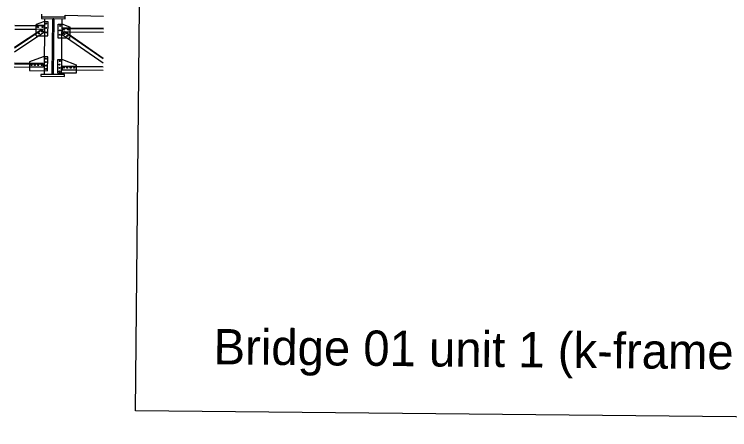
# Model space of a CAD drawing. Extents: x 632066 to 633140, y 373235 to 381884.
# Drawn here: x 632255.8 to 632316.5, y 378317.1 to 378352.4 of the extents above; entities that cross this region are included whole.
import ezdxf

# ---------------------------------------------------------------- set-up
doc = ezdxf.new("R2010")
doc.units = 0
for name, color, linetype in [('B_Boring', 7, 'Continuous'), ('B_Boring Annot', 7, 'Continuous'), ('R_Proposed Const Limits Cut', 7, 'Continuous'), ('R_Proposed Const Limits Fill', 7, 'Continuous'), ('USACE_Easement', 7, 'Continuous')]:
    doc.layers.add(name, color=color, linetype=linetype)

msp = doc.modelspace()

# ---------------------------------------------------------------- linework, layer by layer
at = {"layer": 'B_Boring'}
for p, q in [((632258.246, 378351.771), (632257.618, 378351.527)), ((632258.621, 378351.767), (632258.246, 378351.771)), ((632258.332, 378352.051), (632258.329, 378351.77)), ((632258.609, 378350.58), (632258.621, 378351.767)), ((632259.79, 378352.036), (632259.785, 378351.559)), ((632255.772, 378349.57), (632258.118, 378351.122)), ((632255.773, 378349.62), (632258.095, 378351.157)), ((632255.788, 378351.154), (632257.614, 378351.136)), ((632255.791, 378351.488), (632257.617, 378351.469)), ((632257.611, 378350.837), (632257.618, 378351.527)), ((632258.276, 378350.877), (632258.095, 378351.157)), ((632259.482, 378350.375), (632259.493, 378351.562)), ((632259.493, 378351.562), (632259.868, 378351.558)), ((632259.868, 378351.558), (632260.491, 378351.302)), ((632260.484, 378350.611), (632260.491, 378351.302)), ((632260.491, 378351.244), (632263.325, 378351.216)), ((632255.769, 378349.217), (632258.276, 378350.877)), ((632257.839, 378350.588), (632258.609, 378350.58)), ((632258.317, 378350.578), (632258.299, 378348.787)), ((632259.82, 378350.665), (632260.007, 378350.941)), ((632263.296, 378348.263), (632259.82, 378350.665)), ((632263.3, 378348.616), (632259.984, 378350.907)), ((632263.3, 378348.666), (632260.007, 378350.941)), ((632260.487, 378350.911), (632263.322, 378350.883)), ((632260.252, 378350.367), (632259.482, 378350.375)), ((632259.773, 378350.367), (632259.755, 378348.576)), ((632258.216, 378348.788), (632257.045, 378348.356)), ((632258.591, 378348.784), (632258.216, 378348.788)), ((632258.579, 378347.617), (632258.591, 378348.784)), ((632257.044, 378348.241), (632255.759, 378348.254)), ((632257.045, 378348.356), (632257.038, 378347.633)), ((632259.452, 378347.412), (632259.464, 378348.578)), ((632259.464, 378348.578), (632259.839, 378348.575)), ((632259.839, 378348.575), (632261.001, 378348.12)), ((632261.001, 378348.12), (632260.994, 378347.396)), ((632255.756, 378347.932), (632257.04, 378347.919)), ((632257.038, 378347.633), (632258.579, 378347.617)), ((632258.288, 378347.62), (632258.284, 378347.301)), ((632260.994, 378347.396), (632259.452, 378347.412)), ((632260.997, 378347.683), (632263.29, 378347.66)), ((632261, 378348.005), (632263.25, 378347.983)), ((632259.744, 378347.409), (632259.743, 378347.286))]:
    msp.add_line(p, q, dxfattribs=at)
for points in [[(632260.062, 378352.169), (632258.062, 378352.189), (632258.061, 378352.053), (632260.061, 378352.034)], [(632259.019, 378352.044), (632259.102, 378352.043), (632259.055, 378347.293), (632258.972, 378347.294)], [(632260.013, 378347.284), (632258.014, 378347.304), (632258.012, 378347.147), (632260.012, 378347.128)]]:
    msp.add_lwpolyline(points, close=True, dxfattribs=at)
for centre in [(632258.473, 378351.623), (632257.762, 378351.328), (632258.137, 378351.324), (632258.47, 378351.248), (632259.634, 378351.04), (632259.638, 378351.415), (632259.968, 378351.109), (632260.343, 378351.105), (632257.837, 378350.788), (632258.081, 378350.948), (632258.466, 378350.873), (632259.63, 378350.665), (632260.016, 378350.732), (632260.257, 378350.567), (632258.444, 378348.639), (632257.209, 378348.099), (632257.501, 378348.096), (632257.792, 378348.093), (632258.084, 378348.09), (632258.438, 378348.056), (632258.441, 378348.348), (632259.605, 378348.14), (632259.608, 378348.431), (632258.435, 378347.764), (632259.599, 378347.556), (632259.602, 378347.848), (632259.957, 378347.875), (632260.249, 378347.872), (632260.54, 378347.869), (632260.832, 378347.866)]:
    msp.add_circle(centre, 0.0414, dxfattribs=at)
at = {"layer": 'B_Boring Annot'}
for p, q in [((632258.064, 378352.407), (632258.062, 378352.189)), ((632260.062, 378352.169), (632260.064, 378352.347)), ((632260.064, 378352.347), (632263.336, 378352.249)), ((632258.062, 378352.189), (632260.062, 378352.169))]:
    msp.add_line(p, q, dxfattribs=at)
at = {"layer": 'R_Proposed Const Limits Cut'}
for p, q in [((632258.329, 378351.77), (632258.317, 378350.583)), ((632255.791, 378351.446), (632258.283, 378351.421)), ((632258.281, 378351.129), (632257.614, 378351.136)), ((632258.284, 378351.463), (632257.617, 378351.469)), ((632258.284, 378351.463), (632258.281, 378351.129)), ((632259.785, 378351.559), (632259.773, 378350.372)), ((632259.824, 378351.251), (632259.821, 378350.917)), ((632259.824, 378351.251), (632260.491, 378351.244)), ((632259.824, 378351.209), (632263.325, 378351.174)), ((632257.609, 378350.59), (632257.611, 378350.837)), ((632257.609, 378350.59), (632257.839, 378350.588)), ((632259.821, 378350.917), (632260.487, 378350.911)), ((632260.482, 378350.365), (632260.484, 378350.611)), ((632260.482, 378350.365), (632260.252, 378350.367)), ((632258.299, 378348.787), (632258.288, 378347.62)), ((632255.759, 378348.212), (632258.21, 378348.188)), ((632258.21, 378348.23), (632257.044, 378348.241)), ((632258.21, 378348.23), (632258.207, 378347.907)), ((632259.755, 378348.576), (632259.744, 378347.409)), ((632258.207, 378347.907), (632257.04, 378347.919)), ((632259.833, 378348.017), (632259.83, 378347.694)), ((632259.83, 378347.694), (632260.997, 378347.683)), ((632259.833, 378348.017), (632261, 378348.005)), ((632259.833, 378347.975), (632263.293, 378347.941))]:
    msp.add_line(p, q, dxfattribs=at)
at = {"layer": 'R_Proposed Const Limits Fill'}
msp.add_line((632258.579, 378351.768), (632258.537, 378351.768), dxfattribs=at)
at = {"layer": 'USACE_Easement'}
msp.add_lwpolyline([(632267.311, 378447.311), (632428.73, 378445.706), (632427.452, 378317.129), (632266.032, 378318.734)], close=True, dxfattribs=at)

# ---------------------------------------------------------------- texts
msp.add_text('Bridge 01 unit 1 (k-frame no design)', height=3, rotation=359.43036, dxfattribs=at).set_placement((632272.66, 378322.688))

doc.saveas('drawing.dxf')
